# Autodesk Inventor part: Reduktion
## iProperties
Created: 2005-04
Part Number: Reduktion
Material: Standard
Document SubType Name: Modeling
Designer: M. Sattler
Manufacturer: Standard
Standards Organization: Custom
Author: M. Sattler
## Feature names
1. Sweeping1
2. Sweeping2
